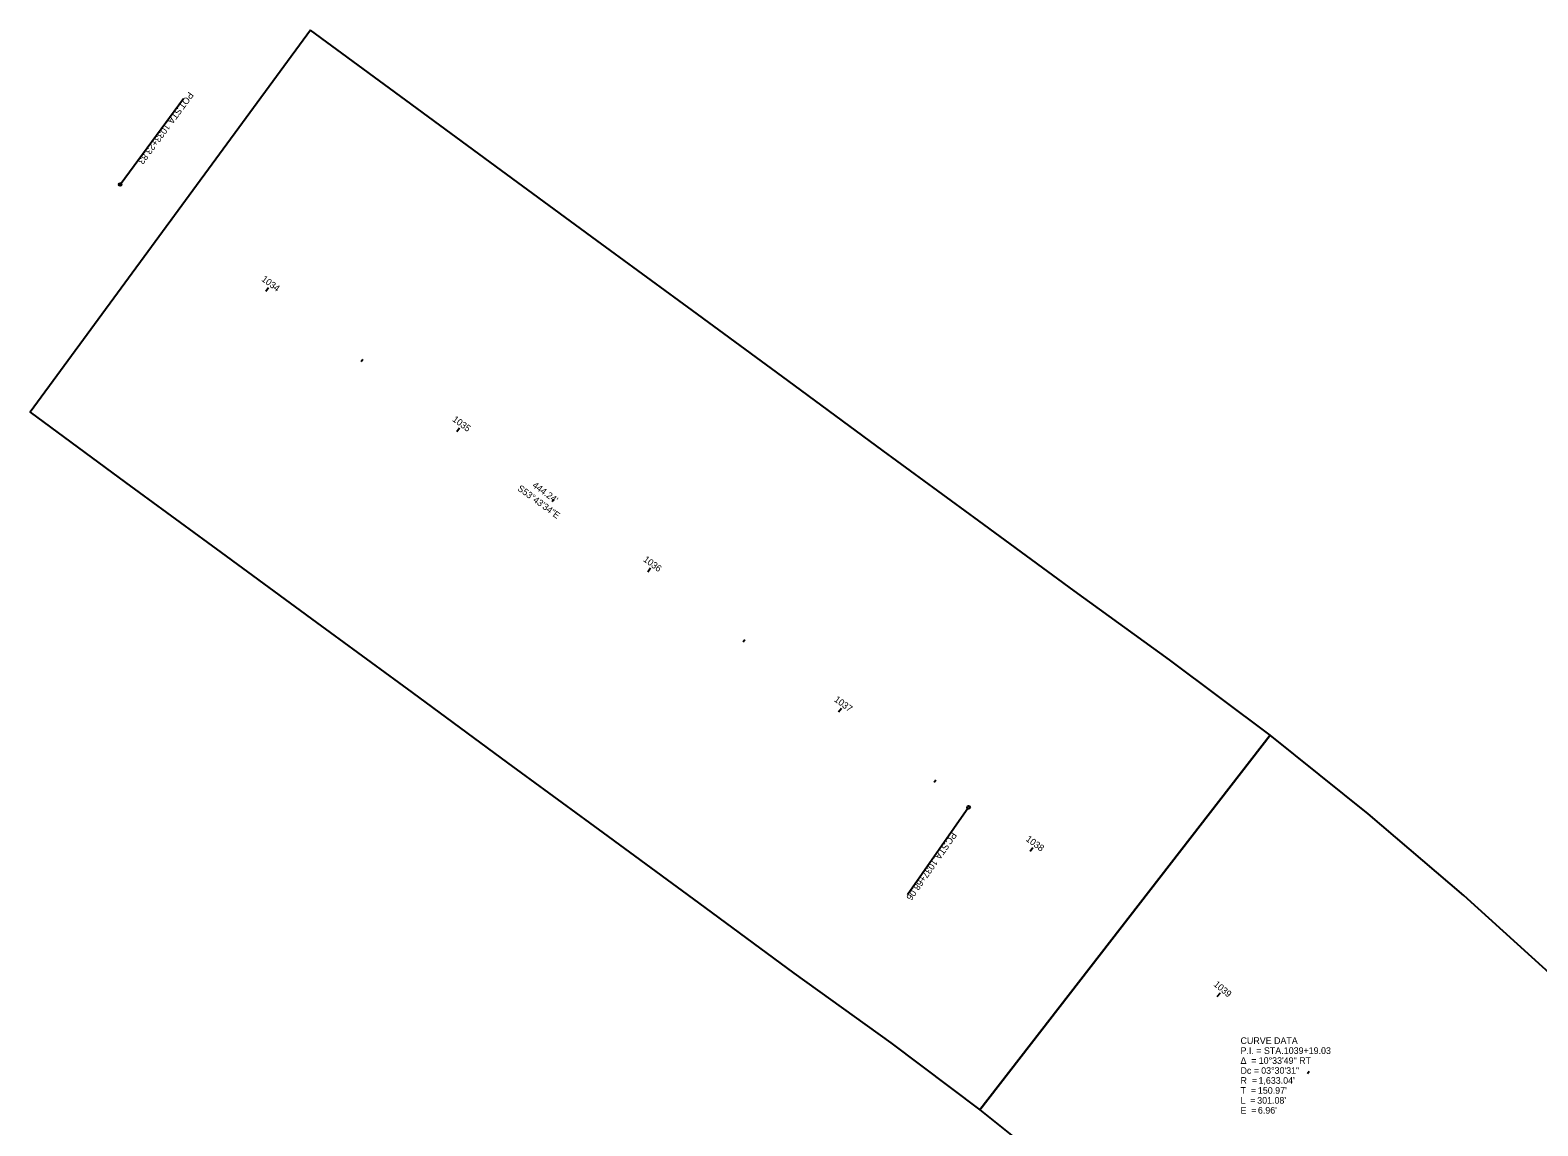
# Model space of a CAD drawing. Extents: x 1846275 to 1850613, y 577927 to 582526.
# Drawn here: x 1846275 to 1846912, y 582064 to 582526 of the extents above; entities that cross this region are included whole.
import ezdxf

# ---------------------------------------------------------------- set-up
doc = ezdxf.new("R2010")
doc.units = 0
for name, color, linetype in [('GE_P_Alignment_100_Cardinal_Points', 7, 'Continuous'), ('PM_P_Cells', 7, 'Continuous'), ('PM_P_Stop_Line', 7, 'Continuous'), ('PM_P_Transverse_Line', 7, 'Continuous'), ('SH_Named_Boundary', 7, 'Continuous'), ('XS_P_Pavt_Surface', 7, 'Continuous')]:
    doc.layers.add(name, color=color, linetype=linetype)

msp = doc.modelspace()

# ---------------------------------------------------------------- linework, layer by layer
at = {"layer": 'GE_P_Alignment_100_Cardinal_Points'}
for p, q in [((1846334.18, 582445.48), (1846334.89, 582446.45)), ((1846374.49, 582415.9), (1846375.68, 582417.51)), ((1846414.8, 582386.31), (1846415.51, 582387.28)), ((1846455.11, 582356.73), (1846456.3, 582358.34)), ((1846495.42, 582327.15), (1846496.13, 582328.12)), ((1846535.73, 582297.57), (1846536.92, 582299.18)), ((1846576.04, 582267.98), (1846576.75, 582268.95)), ((1846616.35, 582238.4), (1846617.54, 582240.01)), ((1846656.66, 582208.82), (1846657.37, 582209.79)), ((1846697.23, 582179.59), (1846698.4, 582181.21)), ((1846737.19, 582149.55), (1846737.93, 582150.49)), ((1846776.22, 582118.29), (1846777.49, 582119.84)), ((1846814.27, 582085.86), (1846815.06, 582086.76))]:
    msp.add_line(p, q, dxfattribs=at)
at = {"layer": 'PM_P_Cells'}
for p, q in [((1846313.08, 582460.96), (1846339.71, 582497.24)), ((1846671.22, 582198.13), (1846645.45, 582161.24))]:
    msp.add_line(p, q, dxfattribs=at)
for centre in [(1846313.08, 582460.96), (1846671.22, 582198.13)]:
    msp.add_circle(centre, 0.6, dxfattribs=at)
at = {"layer": 'SH_Named_Boundary'}
for points in [[(1846393.35, 582526.1), (1846275.02, 582364.86), (1846315.33, 582335.28), (1846355.64, 582305.69), (1846395.95, 582276.11), (1846436.26, 582246.53), (1846476.57, 582216.95), (1846516.88, 582187.36), (1846557.19, 582157.78), (1846597.5, 582128.2), (1846638.37, 582098.74), (1846675.89, 582070.54), (1846798.5, 582228.55), (1846756.09, 582260.43), (1846715.83, 582289.44), (1846675.52, 582319.02), (1846635.21, 582348.6), (1846594.9, 582378.19), (1846554.59, 582407.77), (1846514.28, 582437.35), (1846473.97, 582466.93), (1846433.66, 582496.52)], [(1846798.5, 582228.55), (1846675.89, 582070.54), (1846712.53, 582041.2), (1846748.25, 582010.76), (1846783.02, 581979.23), (1846816.81, 581946.65), (1846852.42, 581911.21), (1846887.96, 581876.05), (1846923.51, 581840.88), (1846959.06, 581805.72), (1846994.6, 581770.56), (1847030.15, 581735.39), (1847170.8, 581877.58), (1847135.26, 581912.74), (1847099.71, 581947.91), (1847064.16, 581983.07), (1847028.62, 582018.23), (1846993.07, 582053.39), (1846957.81, 582088.5), (1846919.61, 582125.33), (1846880.3, 582160.96), (1846839.91, 582195.38)]]:
    msp.add_lwpolyline(points, close=True, dxfattribs=at)

# ---------------------------------------------------------------- texts
at = {"layer": 'GE_P_Alignment_100_Cardinal_Points'}
for s, rotation, p in [('1034', 323.72602, (1846372.43, 582420.51)), ('1035', 323.72602, (1846453.03, 582361.36)), ('1036', 323.72602, (1846533.6, 582302.23)), ('1037', 323.72602, (1846614.18, 582243.1)), ('1038', 323.94401, (1846695.1, 582184.23)), ('1039', 320.43547, (1846774.39, 582123.05))]:
    msp.add_text(s, height=2.8, rotation=rotation, dxfattribs=at).set_placement(p)
at = {"layer": 'PM_P_Cells'}
for s, rotation, p in [('POT', 233.72602, (1846342.01, 582500.32)), (' STA. ', 233.72602, (1846337.75, 582494.51)), ('1033+23.83', 233.72602, (1846332.16, 582486.89)), ('PC', 235.06458, (1846664.17, 582187.96)), (' STA. ', 235.06458, (1846661.54, 582184.2)), ('1037+68.06', 235.06458, (1846656.13, 582176.45))]:
    msp.add_text(s, height=2.8, rotation=rotation, dxfattribs=at).set_placement(p)
at = {"layer": 'PM_P_Stop_Line'}
msp.add_text('S53°43\'34"E', height=2.8, rotation=323.72602, dxfattribs=at).set_placement((1846480.49, 582332.15))
at = {"layer": 'PM_P_Transverse_Line'}
for s, p in [('CURVE DATA', (1846786.02, 582098.27)), ('P.I. = STA. ', (1846786.02, 582094.07)), ('1039+19.03', (1846804.28, 582094.07)), ('Δ  = ', (1846786.02, 582089.87)), ('10°33\'49" RT', (1846793.69, 582089.87)), ('Dc = ', (1846786.02, 582085.67)), ('R  = ', (1846786.02, 582081.47)), ("1,633.04'", (1846793.6, 582081.47)), ('03°30\'31"', (1846794.75, 582085.67)), ('T  = ', (1846786.02, 582077.27)), ("150.97'", (1846793.35, 582077.27)), ('L  = ', (1846786.02, 582073.07)), ('E  = ', (1846786.02, 582068.87)), ("301.08'", (1846793.06, 582073.07)), ("6.96'", (1846793.36, 582068.87))]:
    msp.add_text(s, height=2.8, dxfattribs=at).set_placement(p)
at = {"layer": 'XS_P_Pavt_Surface'}
msp.add_text("444.24'", height=2.8, rotation=323.72602, dxfattribs=at).set_placement((1846486.78, 582333.52))

doc.saveas('drawing.dxf')
